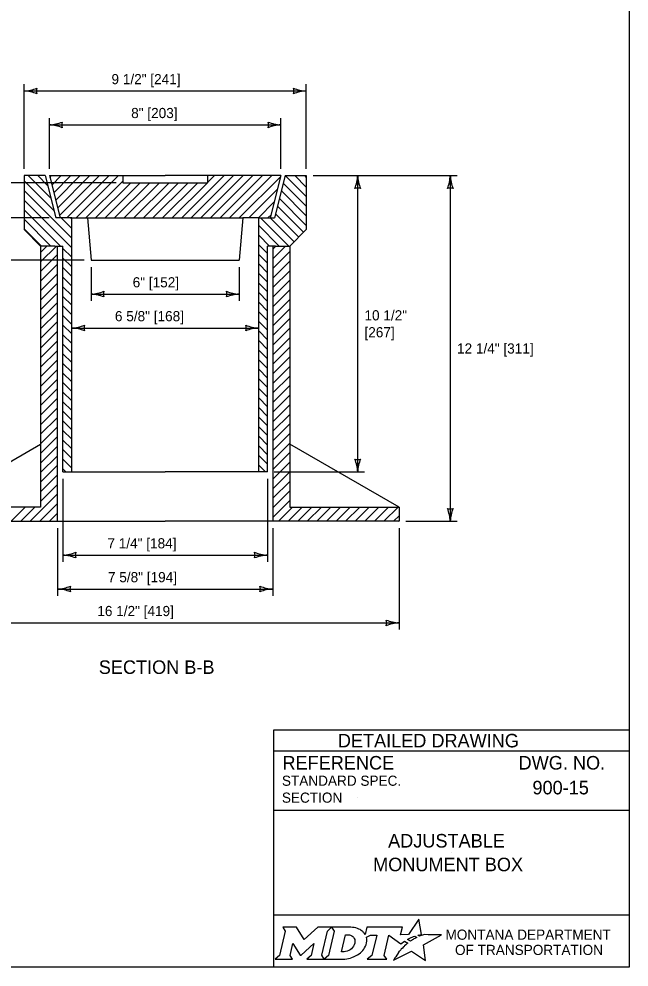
# Model space of a CAD drawing. Extents: x 49991.4 to 50021, y 49987.6 to 50011.4.
# Drawn here: x 50013.15 to 50016.75, y 49987.8 to 49993.4 of the extents above; entities that cross this region are included whole.
import ezdxf

# ---------------------------------------------------------------- set-up
doc = ezdxf.new("R2010")
doc.units = 0
for name, color, linetype in [('Default', 7, 'Continuous'), ('Level 1', 7, 'Continuous'), ('Level 2', 7, 'Continuous'), ('Level 3', 7, 'Continuous'), ('Level 5', 7, 'Continuous')]:
    doc.layers.add(name, color=color, linetype=linetype)

msp = doc.modelspace()

# ---------------------------------------------------------------- linework, layer by layer
at = {"layer": 'Default'}
for points in [[(50015.5126, 49987.9811), (50015.5023, 49987.9867), (50015.5139, 49987.9895), (50015.5255, 49987.9915), (50015.5081, 49988.0816), (50015.4486, 49987.9903), (50015.4013, 49987.9896), (50015.4116, 49988.0337), (50015.2024, 49988.0338), (50015.1923, 49987.9913), (50015.1865, 49987.9996)], [(50014.7056, 49988.0338), (50014.7197, 49988.0104), (50014.6862, 49987.8671), (50014.6605, 49987.8446), (50014.7621, 49987.8446), (50014.7486, 49987.8674), (50014.7648, 49987.9375), (50014.8085, 49987.8685), (50014.8138, 49987.8685), (50014.8889, 49987.938), (50014.8725, 49987.8669), (50014.8478, 49987.8449), (50014.9494, 49987.8449), (50014.9356, 49987.8682), (50014.9688, 49988.0106)], [(50014.9688, 49988.0106), (50014.9941, 49988.0338), (50014.9117, 49988.0338), (50014.8321, 49987.9608), (50014.7876, 49988.0335), (50014.7056, 49988.0338)], [(50015.1077, 49988.0338), (50014.9941, 49988.0338), (50015.0088, 49988.0109), (50014.9749, 49987.8671), (50014.9494, 49987.8449), (50015.06, 49987.8449)], [(50015.1317, 49987.9471), (50015.1305, 49987.939), (50015.1273, 49987.9297), (50015.1231, 49987.9215), (50015.1175, 49987.914), (50015.111, 49987.9071), (50015.1031, 49987.9008), (50015.0948, 49987.8961), (50015.0857, 49987.8922), (50015.0766, 49987.8899), (50015.0674, 49987.889), (50015.0515, 49987.889), (50015.0751, 49987.989), (50015.0911, 49987.989), (50015.0987, 49987.9884), (50015.1063, 49987.9865), (50015.1129, 49987.9835), (50015.119, 49987.9793), (50015.1238, 49987.9743), (50015.1275, 49987.9683), (50015.1302, 49987.9621), (50015.1318, 49987.9547), (50015.1318, 49987.9517), (50015.1317, 49987.9471)], [(50015.1991, 49987.9747), (50015.2237, 49987.9878), (50015.2606, 49987.9878), (50015.232, 49987.8673), (50015.2045, 49987.8446), (50015.3207, 49987.8446), (50015.3037, 49987.8675), (50015.3319, 49987.9877), (50015.4032, 49987.936), (50015.4243, 49987.9511), (50015.444, 49987.9402)], [(50015.3882, 49987.8843), (50015.3729, 49987.8599), (50015.3682, 49987.8524), (50015.3624, 49987.8438), (50015.3601, 49987.8395), (50015.4654, 49987.8926), (50015.5493, 49987.8375), (50015.5362, 49987.9302), (50015.6431, 49987.9886), (50015.5938, 49987.9894), (50015.5637, 49987.9898), (50015.5429, 49987.9901), (50015.5361, 49987.9886), (50015.5312, 49987.9874), (50015.5228, 49987.9851), (50015.5126, 49987.9811)], [(50015.4622, 49987.9535), (50015.4598, 49987.9518), (50015.4415, 49987.9614), (50015.4518, 49987.9671), (50015.4559, 49987.9693), (50015.4645, 49987.9733), (50015.4702, 49987.9759), (50015.4781, 49987.9789), (50015.4854, 49987.9816), (50015.4972, 49987.9742), (50015.4932, 49987.9721), (50015.4886, 49987.9696), (50015.4844, 49987.9674), (50015.4794, 49987.9645), (50015.4775, 49987.9634), (50015.4748, 49987.9618), (50015.4723, 49987.9604), (50015.47, 49987.9588), (50015.4674, 49987.957), (50015.4647, 49987.9552), (50015.4622, 49987.9535)], [(50015.4021, 49987.9004), (50015.4021, 49987.9004)], [(50015.1057, 49987.8522), (50015.1141, 49987.8548), (50015.1271, 49987.8602), (50015.1475, 49987.8712)]]:
    msp.add_lwpolyline(points, dxfattribs=at)
for centre, radius, start, end in [((50015.1308, 49987.9554), 0.0709, 339.5329, 15.8582), ((50015.0868, 49987.9727), 0.1183, 300.9103, 339.1383)]:
    msp.add_arc(centre, radius, start, end, dxfattribs=at)
for centre, major_axis, ratio, start_param, end_param in [((50015.1056, 49987.9864), (0.0834, -0.0037), 0.568097, 0.61298, 1.570796), ((50015.1612, 49987.9937), (0.0361, -0.0295), 0.469099, 1.225588, 1.570796), ((50015.3952, 49987.8923), (-0.00694, -0.00806), 0.008222, 0, 3.137361), ((50015.4119, 49987.9106), (-0.0098, -0.0102), 0.016458, 3.141593, 6.279097), ((50015.4329, 49987.9305), (-0.0112, -0.0097), 0.021651, 3.157348, 6.283185), ((50015.0603, 49987.9932), (0, 0.1484), 0.987302, 3.139398, 3.456847)]:
    msp.add_ellipse(centre, major_axis=major_axis, ratio=ratio, start_param=start_param, end_param=end_param, dxfattribs=at)
at = {"layer": 'Level 1'}
for p, q in [((50013.3028, 49992.4735), (50013.1778, 49992.4735)), ((50013.1778, 49992.4735), (50013.1778, 49992.1547)), ((50013.1778, 49992.442), (50013.355, 49992.2648)), ((50013.2029, 49992.4735), (50013.3362, 49992.3402)), ((50013.2594, 49992.4735), (50013.3173, 49992.4156)), ((50013.3028, 49992.4735), (50013.3653, 49992.2235)), ((50013.3278, 49992.4735), (50013.3903, 49992.2235)), ((50013.3278, 49992.4735), (50014.0112, 49992.4735)), ((50013.3303, 49992.4634), (50013.3405, 49992.4735)), ((50013.3416, 49992.4181), (50013.397, 49992.4735)), ((50013.353, 49992.3729), (50013.4536, 49992.4735)), ((50013.3643, 49992.3276), (50013.5102, 49992.4735)), ((50013.3756, 49992.2823), (50013.5667, 49992.4735)), ((50013.3869, 49992.2371), (50013.6233, 49992.4735)), ((50013.4299, 49992.2235), (50013.6799, 49992.4735)), ((50013.4864, 49992.2235), (50013.7364, 49992.4735)), ((50013.543, 49992.2235), (50013.7612, 49992.4417)), ((50013.5996, 49992.2235), (50013.8079, 49992.4318)), ((50013.6562, 49992.2235), (50013.8645, 49992.4318)), ((50013.7127, 49992.2235), (50013.9211, 49992.4318)), ((50013.7612, 49992.4735), (50013.7612, 49992.4318)), ((50013.7612, 49992.4318), (50014.2612, 49992.4318)), ((50013.7693, 49992.2235), (50013.9776, 49992.4318)), ((50013.8259, 49992.2235), (50014.0342, 49992.4318)), ((50013.8824, 49992.2235), (50014.0908, 49992.4318)), ((50013.939, 49992.2235), (50014.1473, 49992.4318)), ((50013.9956, 49992.2235), (50014.2039, 49992.4318)), ((50014.6946, 49992.4735), (50014.0112, 49992.4735)), ((50014.0521, 49992.2235), (50014.2605, 49992.4318)), ((50014.1087, 49992.2235), (50014.3587, 49992.4735)), ((50014.1653, 49992.2235), (50014.4153, 49992.4735)), ((50014.2218, 49992.2235), (50014.4718, 49992.4735)), ((50014.2612, 49992.4735), (50014.2612, 49992.4318)), ((50014.2612, 49992.4326), (50014.3021, 49992.4735)), ((50014.2784, 49992.2235), (50014.5284, 49992.4735)), ((50014.335, 49992.2235), (50014.585, 49992.4735)), ((50014.3915, 49992.2235), (50014.6415, 49992.4735)), ((50014.4481, 49992.2235), (50014.6934, 49992.4688)), ((50014.6946, 49992.4735), (50014.6321, 49992.2235)), ((50014.7195, 49992.4735), (50014.657, 49992.2235)), ((50014.7084, 49992.4292), (50014.8445, 49992.2931)), ((50014.7195, 49992.4735), (50014.8445, 49992.4735)), ((50014.7206, 49992.4735), (50014.8445, 49992.3496)), ((50014.7772, 49992.4735), (50014.8445, 49992.4062)), ((50014.8338, 49992.4735), (50014.8445, 49992.4628)), ((50014.8445, 49992.4735), (50014.8445, 49992.1547)), ((50013.1778, 49992.3854), (50013.4591, 49992.1041)), ((50014.5047, 49992.2235), (50014.6745, 49992.3933)), ((50014.6971, 49992.3839), (50014.8445, 49992.2365)), ((50013.1778, 49992.3288), (50013.4591, 49992.0476)), ((50014.5613, 49992.2235), (50014.6557, 49992.3179)), ((50014.6858, 49992.3386), (50014.8445, 49992.1799)), ((50013.1778, 49992.2723), (50013.3933, 49992.0568)), ((50014.6745, 49992.2934), (50014.8288, 49992.139)), ((50013.1778, 49992.2157), (50013.3367, 49992.0568)), ((50013.4591, 49992.2235), (50013.3653, 49992.2235)), ((50013.3963, 49992.2235), (50013.4591, 49992.1607)), ((50013.4529, 49992.2235), (50013.4591, 49992.2173)), ((50013.4591, 49990.7235), (50013.4591, 49992.2235)), ((50013.4591, 49992.2235), (50013.5517, 49992.2235)), ((50013.5517, 49992.2235), (50013.5736, 49991.9735)), ((50013.5517, 49992.2235), (50014.4706, 49992.2235)), ((50014.4706, 49992.2235), (50014.4487, 49991.9735)), ((50014.5633, 49992.2235), (50014.4706, 49992.2235)), ((50014.5633, 49990.7235), (50014.5633, 49992.2235)), ((50014.5633, 49992.2235), (50014.657, 49992.2235)), ((50014.5747, 49992.2235), (50014.7413, 49992.0568)), ((50014.6178, 49992.2235), (50014.6368, 49992.2425)), ((50014.6312, 49992.2235), (50014.7723, 49992.0825)), ((50014.6632, 49992.2481), (50014.8006, 49992.1107)), ((50013.1778, 49992.1591), (50013.2801, 49992.0568)), ((50013.2757, 49992.0568), (50013.1778, 49992.1547)), ((50014.5633, 49992.1783), (50014.6848, 49992.0568)), ((50014.7466, 49992.0568), (50014.8445, 49992.1547)), ((50014.5633, 49992.1218), (50014.6282, 49992.0568)), ((50013.359, 49992.0568), (50013.2757, 49992.0568)), ((50013.2757, 49992.0568), (50013.2757, 49990.5152)), ((50013.2757, 49992.0203), (50013.3123, 49992.0568)), ((50013.2757, 49991.9637), (50013.3688, 49992.0568)), ((50013.359, 49992.0568), (50013.407, 49992.0568)), ((50013.3758, 49990.4318), (50013.3758, 49992.0568)), ((50013.407, 49990.7235), (50013.407, 49992.0568)), ((50013.407, 49992.0431), (50013.4591, 49991.991)), ((50014.5633, 49992.0652), (50014.6153, 49992.0131)), ((50014.6633, 49992.0568), (50014.6153, 49992.0568)), ((50014.6153, 49990.7235), (50014.6153, 49992.0568)), ((50014.6466, 49992.0568), (50014.6466, 49990.4318)), ((50014.6466, 49992.0383), (50014.6652, 49992.0568)), ((50014.6466, 49991.9817), (50014.7217, 49992.0568)), ((50014.6633, 49992.0568), (50014.7466, 49992.0568)), ((50014.7466, 49992.0568), (50014.7466, 49990.5152)), ((50013.2757, 49991.9071), (50013.3758, 49992.0072)), ((50013.407, 49991.9865), (50013.4591, 49991.9344)), ((50014.5633, 49992.0086), (50014.6153, 49991.9565)), ((50014.6466, 49991.9252), (50014.7466, 49992.0252)), ((50013.2757, 49991.8506), (50013.3758, 49991.9506)), ((50013.407, 49991.93), (50013.4591, 49991.8779)), ((50013.5736, 49991.9735), (50014.4487, 49991.9735)), ((50014.5633, 49991.9521), (50014.6153, 49991.9)), ((50014.6466, 49991.8686), (50014.7466, 49991.9686)), ((50013.2757, 49991.794), (50013.3758, 49991.894)), ((50013.407, 49991.8734), (50013.4591, 49991.8213)), ((50014.5633, 49991.8955), (50014.6153, 49991.8434)), ((50014.6466, 49991.812), (50014.7466, 49991.912)), ((50013.2757, 49991.7374), (50013.3758, 49991.8375)), ((50013.407, 49991.8168), (50013.4591, 49991.7647)), ((50014.5633, 49991.8389), (50014.6153, 49991.7868)), ((50014.6466, 49991.7555), (50014.7466, 49991.8555)), ((50013.2757, 49991.6809), (50013.3758, 49991.7809)), ((50013.407, 49991.7602), (50013.4591, 49991.7082)), ((50014.5633, 49991.7824), (50014.6153, 49991.7303)), ((50014.6466, 49991.6989), (50014.7466, 49991.7989)), ((50013.2757, 49991.6243), (50013.3758, 49991.7243)), ((50013.407, 49991.7037), (50013.4591, 49991.6516)), ((50014.5633, 49991.7258), (50014.6153, 49991.6737)), ((50014.6466, 49991.6423), (50014.7466, 49991.7423)), ((50013.2757, 49991.5677), (50013.3758, 49991.6678)), ((50013.407, 49991.6471), (50013.4591, 49991.595)), ((50014.5633, 49991.6692), (50014.6153, 49991.6171)), ((50014.6466, 49991.5858), (50014.7466, 49991.6858)), ((50013.2757, 49991.5112), (50013.3758, 49991.6112)), ((50013.407, 49991.5905), (50013.4591, 49991.5385)), ((50014.5633, 49991.6127), (50014.6153, 49991.5606)), ((50014.6466, 49991.5292), (50014.7466, 49991.6292)), ((50013.2757, 49991.4546), (50013.3758, 49991.5546)), ((50013.407, 49991.534), (50013.4591, 49991.4819)), ((50014.5633, 49991.5561), (50014.6153, 49991.504)), ((50014.6466, 49991.4726), (50014.7466, 49991.5726)), ((50013.2757, 49991.398), (50013.3758, 49991.4981)), ((50013.407, 49991.4774), (50013.4591, 49991.4253)), ((50014.5633, 49991.4995), (50014.6153, 49991.4474)), ((50014.6466, 49991.416), (50014.7466, 49991.516)), ((50013.2757, 49991.3414), (50013.3758, 49991.4415)), ((50013.407, 49991.4208), (50013.4591, 49991.3688)), ((50014.5633, 49991.4429), (50014.6153, 49991.3909)), ((50014.6466, 49991.3595), (50014.7466, 49991.4595)), ((50013.2757, 49991.2849), (50013.3758, 49991.3849)), ((50013.407, 49991.3643), (50013.4591, 49991.3122)), ((50014.5633, 49991.3864), (50014.6153, 49991.3343)), ((50014.6466, 49991.3029), (50014.7466, 49991.4029)), ((50013.2757, 49991.2283), (50013.3758, 49991.3284)), ((50013.407, 49991.3077), (50013.4591, 49991.2556)), ((50014.5633, 49991.3298), (50014.6153, 49991.2777)), ((50014.6466, 49991.2463), (50014.7466, 49991.3463)), ((50013.2757, 49991.1717), (50013.3758, 49991.2718)), ((50013.407, 49991.2511), (50013.4591, 49991.199)), ((50014.5633, 49991.2732), (50014.6153, 49991.2212)), ((50014.6466, 49991.1898), (50014.7466, 49991.2898)), ((50013.2757, 49991.1152), (50013.3758, 49991.2152)), ((50013.407, 49991.1946), (50013.4591, 49991.1425)), ((50014.5633, 49991.2167), (50014.6153, 49991.1646)), ((50014.6466, 49991.1332), (50014.7466, 49991.2332)), ((50013.2757, 49991.0586), (50013.3758, 49991.1587)), ((50013.407, 49991.138), (50013.4591, 49991.0859)), ((50014.5633, 49991.1601), (50014.6153, 49991.108)), ((50014.6466, 49991.0766), (50014.7466, 49991.1766)), ((50013.2757, 49991.002), (50013.3758, 49991.1021)), ((50013.407, 49991.0814), (50013.4591, 49991.0293)), ((50014.5633, 49991.1035), (50014.6153, 49991.0515)), ((50014.6466, 49991.0201), (50014.7466, 49991.1201)), ((50013.2757, 49990.9455), (50013.3758, 49991.0455)), ((50014.5633, 49991.047), (50014.6153, 49990.9949)), ((50014.6466, 49990.9635), (50014.7466, 49991.0635)), ((50013.2757, 49990.8889), (50013.3758, 49990.9889)), ((50013.407, 49991.0249), (50013.4591, 49990.9728)), ((50014.5633, 49990.9904), (50014.6153, 49990.9383)), ((50014.6466, 49990.9069), (50014.7466, 49991.0069)), ((50013.2757, 49990.8323), (50013.3758, 49990.9324)), ((50013.407, 49990.9683), (50013.4591, 49990.9162)), ((50014.5633, 49990.9338), (50014.6153, 49990.8817)), ((50014.6466, 49990.8504), (50014.7466, 49990.9504)), ((50012.6299, 49990.5152), (50013.2757, 49990.888)), ((50013.2757, 49990.7758), (50013.3758, 49990.8758)), ((50013.407, 49990.9117), (50013.4591, 49990.8596)), ((50014.5633, 49990.8773), (50014.6153, 49990.8252)), ((50014.6466, 49990.7938), (50014.7466, 49990.8938)), ((50015.3925, 49990.5152), (50014.7466, 49990.888)), ((50013.2757, 49990.7192), (50013.3758, 49990.8192)), ((50013.407, 49990.8552), (50013.4591, 49990.8031)), ((50014.5633, 49990.8207), (50014.6153, 49990.7686)), ((50014.6466, 49990.7372), (50014.7466, 49990.8372)), ((50013.2757, 49990.6626), (50013.3758, 49990.7627)), ((50013.407, 49990.7986), (50013.4591, 49990.7465)), ((50014.5633, 49990.7641), (50014.6039, 49990.7235)), ((50014.6466, 49990.6807), (50014.7466, 49990.7807)), ((50013.2757, 49990.6061), (50013.3758, 49990.7061)), ((50013.407, 49990.742), (50013.4255, 49990.7235)), ((50013.407, 49990.7235), (50013.4591, 49990.7235)), ((50013.4591, 49990.7235), (50014.0112, 49990.7235)), ((50014.5633, 49990.7235), (50014.0112, 49990.7235)), ((50014.6153, 49990.7235), (50014.5633, 49990.7235)), ((50014.6466, 49990.6241), (50014.7466, 49990.7241)), ((50013.2757, 49990.5495), (50013.3758, 49990.6495)), ((50014.6466, 49990.5675), (50014.7466, 49990.6675)), ((50013.2146, 49990.4318), (50013.3758, 49990.593)), ((50014.6466, 49990.511), (50014.7466, 49990.611)), ((50013.2712, 49990.4318), (50013.3758, 49990.5364)), ((50014.6466, 49990.4544), (50014.7466, 49990.5544)), ((50013.2757, 49990.5152), (50012.6299, 49990.5152)), ((50013.1015, 49990.4318), (50013.1848, 49990.5152)), ((50013.158, 49990.4318), (50013.2414, 49990.5152)), ((50013.3278, 49990.4318), (50013.3758, 49990.4798)), ((50014.6807, 49990.4318), (50014.764, 49990.5152)), ((50014.7372, 49990.4318), (50014.8206, 49990.5152)), ((50014.7466, 49990.5152), (50015.3925, 49990.5152)), ((50014.7938, 49990.4318), (50014.8771, 49990.5152)), ((50014.8504, 49990.4318), (50014.9337, 49990.5152)), ((50014.9069, 49990.4318), (50014.9903, 49990.5152)), ((50014.9635, 49990.4318), (50015.0468, 49990.5152)), ((50015.0201, 49990.4318), (50015.1034, 49990.5152)), ((50015.0766, 49990.4318), (50015.16, 49990.5152)), ((50015.1332, 49990.4318), (50015.2165, 49990.5152)), ((50015.1898, 49990.4318), (50015.2731, 49990.5152)), ((50015.2463, 49990.4318), (50015.3297, 49990.5152)), ((50015.3029, 49990.4318), (50015.3862, 49990.5152)), ((50015.3925, 49990.5152), (50015.3925, 49990.4318)), ((50012.6299, 49990.4318), (50013.359, 49990.4318)), ((50013.359, 49990.4318), (50014.0112, 49990.4318)), ((50014.6633, 49990.4318), (50014.0112, 49990.4318)), ((50015.3925, 49990.4318), (50014.6633, 49990.4318)), ((50015.3595, 49990.4318), (50015.3925, 49990.4648)), ((50015.3872, 49990.4318), (50015.3925, 49990.4371))]:
    msp.add_line(p, q, dxfattribs=at)
msp.add_lwpolyline([(49999.3835, 49998.9992), (50016.7501, 49998.9992), (50016.7501, 49987.7988), (49999.3835, 49987.7988)], close=True, dxfattribs=at)
at = {"layer": 'Level 3'}
for p, q in [((50013.1778, 49992.5135), (50013.1778, 49993.0135)), ((50014.8445, 49992.5135), (50014.8445, 49993.0135)), ((50013.1778, 49992.9735), (50014.8445, 49992.9735)), ((50013.3278, 49992.5135), (50013.3278, 49992.8135)), ((50013.3278, 49992.7735), (50014.6946, 49992.7735)), ((50014.6946, 49992.5135), (50014.6946, 49992.8135)), ((50013.2521, 49992.4318), (50012.9378, 49992.4318)), ((50013.7212, 49992.4318), (50013.2521, 49992.4318)), ((50014.8845, 49992.4735), (50015.7345, 49992.4735)), ((50015.148, 49990.7235), (50015.148, 49992.4735)), ((50015.6945, 49992.4735), (50015.6945, 49990.4318)), ((50013.3253, 49992.2235), (50012.2577, 49992.2235)), ((50013.5336, 49991.9735), (50011.8609, 49991.9735)), ((50013.5736, 49991.9335), (50013.5736, 49991.7335)), ((50014.4487, 49991.9335), (50014.4487, 49991.7335)), ((50013.5736, 49991.7735), (50014.4487, 49991.7735)), ((50013.4591, 49991.5735), (50014.5633, 49991.5735)), ((50014.6553, 49990.7235), (50015.188, 49990.7235)), ((50013.407, 49990.6835), (50013.407, 49990.1918)), ((50014.6153, 49990.6835), (50014.6153, 49990.1918)), ((50015.4325, 49990.4318), (50015.7345, 49990.4318)), ((50013.3758, 49990.3918), (50013.3758, 49989.9918)), ((50014.6465, 49990.3918), (50014.6465, 49989.9918)), ((50015.3925, 49990.3918), (50015.3925, 49989.7918)), ((50013.407, 49990.2318), (50014.6153, 49990.2318)), ((50013.3758, 49990.0318), (50014.6465, 49990.0318)), ((50012.6299, 49989.8318), (50015.3925, 49989.8318))]:
    msp.add_line(p, q, dxfattribs=at)
for centre, radius, start, end in [((50013.1663, 49993.2062), 0.233, 272.8273, 292.0772), ((50013.3061, 49992.9735), 0.0548, 162.1388, 197.8612), ((50014.8537, 49993.1956), 0.2223, 247.456, 267.6395), ((50014.7163, 49992.9735), 0.0548, 342.1388, 17.8612), ((50013.1687, 49992.7514), 0.2223, 67.456, 87.6395), ((50014.856, 49992.7408), 0.233, 92.8273, 112.0772), ((50013.3163, 49993.0062), 0.233, 272.8273, 292.0772), ((50013.3186, 49992.5514), 0.2223, 67.456, 87.6395), ((50013.456, 49992.7735), 0.0548, 162.1388, 197.8612), ((50014.7037, 49992.9956), 0.2223, 247.456, 267.6395), ((50014.5663, 49992.7735), 0.0548, 342.1388, 17.8612), ((50014.706, 49992.5408), 0.233, 92.8273, 112.0772), ((50014.9258, 49992.4827), 0.2223, 337.456, 357.6395), ((50015.3807, 49992.485), 0.233, 182.8273, 202.0772), ((50015.4724, 49992.4827), 0.2223, 337.456, 357.6395), ((50015.9272, 49992.485), 0.233, 182.8273, 202.0772), ((50015.148, 49992.3453), 0.0548, 72.1388, 107.8612), ((50015.6945, 49992.3453), 0.0548, 72.1388, 107.8612), ((50013.5621, 49992.0062), 0.233, 272.8273, 292.0772), ((50013.5645, 49991.5514), 0.2223, 67.456, 87.6395), ((50013.7018, 49991.7735), 0.0548, 162.1388, 197.8612), ((50014.4579, 49991.9956), 0.2223, 247.456, 267.6395), ((50014.3205, 49991.7735), 0.0548, 342.1388, 17.8612), ((50014.4602, 49991.5408), 0.233, 92.8273, 112.0772), ((50013.4476, 49991.8062), 0.233, 272.8273, 292.0772), ((50013.5873, 49991.5735), 0.0548, 162.1388, 197.8612), ((50014.5724, 49991.7956), 0.2223, 247.456, 267.6395), ((50014.435, 49991.5735), 0.0548, 342.1388, 17.8612), ((50013.4499, 49991.3514), 0.2223, 67.456, 87.6395), ((50014.5747, 49991.3408), 0.233, 92.8273, 112.0772), ((50015.148, 49990.8517), 0.0548, 252.1388, 287.8612), ((50014.9153, 49990.712), 0.233, 2.8273, 22.0772), ((50015.3701, 49990.7144), 0.2223, 157.456, 177.6395), ((50015.6945, 49990.56), 0.0548, 252.1388, 287.8612), ((50015.4618, 49990.4203), 0.233, 2.8273, 22.0772), ((50015.9166, 49990.4227), 0.2223, 157.456, 177.6395), ((50013.3955, 49990.4645), 0.233, 272.8273, 292.0772), ((50013.5352, 49990.2318), 0.0548, 162.1388, 197.8612), ((50014.6245, 49990.454), 0.2223, 247.456, 267.6395), ((50014.4871, 49990.2318), 0.0548, 342.1388, 17.8612), ((50013.3978, 49990.0097), 0.2223, 67.456, 87.6395), ((50014.6268, 49989.9991), 0.233, 92.8273, 112.0772), ((50013.3643, 49990.2645), 0.233, 272.8273, 292.0772), ((50013.3666, 49989.8097), 0.2223, 67.456, 87.6395), ((50013.504, 49990.0318), 0.0548, 162.1388, 197.8612), ((50014.6557, 49990.254), 0.2223, 247.456, 267.6395), ((50014.5183, 49990.0318), 0.0548, 342.1388, 17.8612), ((50014.658, 49989.7991), 0.233, 92.8273, 112.0772), ((50015.4016, 49990.054), 0.2223, 247.456, 267.6395), ((50015.2643, 49989.8318), 0.0548, 342.1388, 17.8612), ((50015.404, 49989.5991), 0.233, 92.8273, 112.0772)]:
    msp.add_arc(centre, radius, start, end, dxfattribs=at)
at = {"layer": 'Level 5'}
for p, q in [((50016.7501, 49989.1988), (50014.6501, 49989.1988)), ((50014.6501, 49989.1988), (50014.6501, 49987.7988)), ((50016.7501, 49989.0738), (50014.6501, 49989.0738)), ((50016.3862, 49988.8587), (50016.3862, 49988.8587)), ((50015.1444, 49988.7993), (50015.1444, 49988.7993)), ((50016.7501, 49988.7238), (50014.6501, 49988.7238)), ((50015.7001, 49988.4747), (50015.7001, 49988.4747)), ((50016.7501, 49988.1057), (50014.6501, 49988.1057))]:
    msp.add_line(p, q, dxfattribs=at)

# ---------------------------------------------------------------- texts
at = {"layer": 'Default'}
for s, p in [('MONTANA DEPARTMENT', (50015.6663, 49987.96)), ('OF TRANSPORTATION', (50015.7225, 49987.87))]:
    msp.add_text(s, height=0.06, dxfattribs=at).set_placement(p)
at = {"layer": 'Level 2'}
for s, height, p in [('9 1/2" [241]', 0.06, (50013.6943, 49993.0135)), ('8" [203]', 0.06, (50013.8105, 49992.8135)), ('6" [152]', 0.06, (50013.8194, 49991.8135)), ('6 5/8" [168]', 0.06, (50013.7146, 49991.6135)), ('10 1/2"', 0.06, (50015.188, 49991.6185)), ('[267]', 0.06, (50015.188, 49991.5185)), ('12 1/4" [311]', 0.06, (50015.7345, 49991.4227)), ('7 1/4" [184]', 0.06, (50013.6703, 49990.2718)), ('7 5/8" [194]', 0.06, (50013.6734, 49990.0718)), ('16 1/2" [419]', 0.06, (50013.6106, 49989.8718)), ('SECTION B-B', 0.08, (50013.6191, 49989.5302)), ('900-15', 0.08, (50016.1798, 49988.8187)), ('ADJUSTABLE', 0.08, (50015.3276, 49988.5047)), ('MONUMENT BOX', 0.08, (50015.239, 49988.3647))]:
    msp.add_text(s, height=height, dxfattribs=at).set_placement(p)
at = {"layer": 'Level 5'}
for s, height, p in [('DETAILED DRAWING', 0.0799, (50015.0311, 49989.0963)), ('REFERENCE', 0.08, (50014.7037, 49988.9654)), ('DWG. NO.', 0.08, (50016.0979, 49988.9654)), ('STANDARD SPEC.', 0.06, (50014.7004, 49988.8694)), ('SECTION', 0.06, (50014.7004, 49988.7694))]:
    msp.add_text(s, height=height, dxfattribs=at).set_placement(p)

doc.saveas('drawing.dxf')
